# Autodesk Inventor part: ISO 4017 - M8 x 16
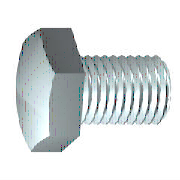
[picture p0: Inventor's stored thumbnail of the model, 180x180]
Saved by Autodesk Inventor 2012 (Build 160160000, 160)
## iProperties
Company: CAD-Verlag
Comments: To add or edit properties for Autodesk Inventor files, use iProperties.
Shininess: 64.0
Length Units: 11269
Angle Units: 11279
Time Units: 11290
Mass Units: 11283
Length Display Precision: 3
Angle Display Precision: 2
Compacted: True
Alert: To add or edit properties for Autodesk Inventor files, use iProperties.
Created: 2004-09
Part Number: ISO 4017 - M8 x 16
Vendor: Autodesk Inc.
Document SubType Name: Modeling
Designer: Greiling
Material: Standard
Description: Sechskantschraube
Standard: ISO 4017
Size Designation: M8 x 16
Density: 1 g/cm^3
Density: 0.0
Volumn: 0.0
Area: 0.0
PropertySet Name: Model Information
Control State: 0
Master: False
Checked Out: False
EGR: 1
Author: Jürgen Kronas
Revision Number: 8
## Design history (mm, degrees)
revolve "Körper" stored, may be unused: angle "d12" = 90 deg
sketch "Skizze2"
  geometry: L1 (0, 7.506)-(6.5, 3.753); L2 (6.5, 3.753)-(6.5, -3.753); L3 (6.5, -3.753)-(0, -7.506); L4 (0, -7.506)-(-6.5, -3.753); L5 (-6.5, -3.753)-(-6.5, 3.753); L6 (-6.5, 3.753)-(0, 7.506); 2 further points
  constraints: 12 end point, 1 coincident, 1 vertical, 11 other
  dimensions: "d11" = 13 distance between parallel lines of L5 L2 (= SW)
extrude "Kopf" join sketch "Skizze2" distance "d3" = 4.7 (= KOH - SD); taper "d4" = 0 deg
revolve "Fase1" stored, may be unused: angle "d21" = 90 deg
node "Volumenkörper1"
node "Volumenkörpern"
node "Oberflächenkörpern"
feature "Gewinde" dims "d15" = 12 (= GEL), "d16" = 0
chamfer "Fase2" distance "d6" = 0.76681 (= -0.5 x SPD + 0.5 x GD); stored, may be unused: second distance "d7" = 0.76691 (computed from GUL), angle "d55" = 45 deg
sketch "Skizze1"
  geometry: L1 (0, 5.815)-(0, 4); L2 (4, 4)-(16, 4); L3 (16, 4)-(16, 0); L4 (16, 0)-(-0.6, 0); L5 (-2.26, 0)-(20.98, 0) reference; L6 (-0.6, 0)-(-0.6, 5.815); L7 (-0.6, 5.815)-(0, 5.815); L8 (4, 4)-(3.233, 4); L9 (3.233, 4)-(0, 4); L10 (0, -0.582)-(0, 7.559) reference
  constraints: 16 end point, 2 collinear, 2 perpendicular, 1 parallel
  dimensions: "d0" = 16 distance between parallel lines of L3 L1 (= NLG); "d1" = 12 distance from line of L2.start L3 (= GEL); "d2" = 8 diameter of L2 L4 (= GD); "d9" = 0.6001 distance between parallel lines of L6 L1 (computed from SD); "d10" = 11.63 diameter of L7 L4 (= SD2); "d13" = 0.76691 distance of L2.start L8.end (computed from GAL); "d14" = 8 diameter of L9 L4 (= BDM)
sketch "Skizze4"
  geometry: L1 (-5.3, 6.5)-(-5.3, 7.506); L2 (-5.3, 7.506)-(-4.72, 7.506); L3 (-4.72, 7.506)-(-5.3, 6.5); L4 (-5.77, 0)-(0.81, 0) reference; L5 (-0.6, 7.506)-(-5.3, 7.506) reference; L6 (-5.3, 3.753)-(-5.3, 7.506) reference
  constraints: 6 end point, 2 collinear, 1 perpendicular, 1 vertical
  dimensions: "d5" = 30 deg angle of L3 L1 (= ANG1); "d19" = 13 diameter of L1.start L4 (= SW0)
other parameters: "NLG" = 16 [user parameter; used in 2 equation terms], "GD" = 8 (= NND) [user parameter; used in 2 equation terms], "BDM" = 8 (= NND) [user parameter; used in 1 equation term], "KOH" = 5.3 [user parameter; used in 1 equation term], "GEL" = 12 [user parameter; used in 2 equation terms], "SW" = 13 [user parameter; used in 2 equation terms], "SW0" = 13 (= SW) [user parameter; used in 1 equation term], "SPD" = 6.46637 (= NND - 1.2269 x TPU) [user parameter; used in 1 equation term], "SD2" = 11.63 [user parameter; used in 2 equation terms], "SD" = 0.6 [user parameter; used in 2 equation terms], "ANG1" = 30 deg [user parameter; used in 1 equation term], "GAL" = 0.76681 (= 0.61345 x TPU) [user parameter; used in 1 equation term], "GUL" = 0.76681 (= 0.61345 x TPU) [user parameter; used in 1 equation term], "d8" = 0, "RR" = 0.4 [user parameter], "d20" = -16 (= -NLG), "NND" = 8 [user parameter; used in 3 equation terms], "SDHG" = 4 [user parameter], "E0" = 15.015 [user parameter], "SDH" = 11.63 (= SD2) [user parameter], "THREADDIA" = 8 [user parameter; used in 1 equation term], "TPU" = 1.25 [user parameter; used in 5 equation terms], "GD1" = 6.46637 (= THREADDIA - 1.2269 x TPU) [user parameter], "PTC" = 1.25 (= TPU) [user parameter], "TOA" = 30 deg [user parameter]
